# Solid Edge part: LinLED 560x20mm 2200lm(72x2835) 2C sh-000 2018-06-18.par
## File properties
Subject: LinLED 560x20mm 2200lm(72x2835) 2C
Author: radoslaw.kuczynski
Template: iso metric part.par
Last saved by: radoslaw.kuczynski
Revision: 2
Application: Solid Edge
Username: radoslaw.kuczynski
Gęstość: 0,000 kg/m^3
Dokładność: 0,990
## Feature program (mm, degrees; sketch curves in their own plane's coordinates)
body "unnamed Body 1"
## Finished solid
Body 1: solid body, 1821 faces, 4718 edges, 3074 vertices, 3 separate solids.
  Faces by surface: plane 1492, cylinder 147, spline 96, cone 30, swept 22, sphere 16, torus 10, spun 8
  Edges by curve: line 4024, curve on surface 358, circle 206, ellipse 66, spline 60, intersection 4
Bounding box of the edges (mm; curved faces can reach further): 560.000 x 4.500 x 20.000, from (-280, -3.5, -10) to (280, 1, 10).
Cylindrical faces by radius (mm): R0.2 x46, R0.2169 x6, R0.25 x12, R0.3373 x6, R0.4 x8, R0.4006 x2, R0.4008 x2, R0.525 x2, R0.6 x20, R0.75 x1, R1 x8, R1.1 x4, R1.2 x10, R2.15 x20
Conical faces (half-angle, radius in mm at the cone's reference point): 0.5 deg R0.5056 x4, 0.5 deg R1.0082 x4, 1 deg R0.5511 x2, 10 deg R0.2132 x4, 10 deg R0.4132 x4, 18.8604 deg R1.0669 x4, 27.363 deg R0.6214 x2, 45 deg R0.575 x2, 45 deg R0.625 x4
Toroidal faces (ring radius, tube radius in mm): R0.8 r0.2 x4, R0.8522 r0.3 x2, R0.9002 r0.2 x2, R0.9018 r0.2 x2
Spherical faces by radius (mm): R0.2 x12, R0.6 x4
Planar faces by outward normal: +x 191, +y 13, +z 191, -x 191, -y 259, -z 193, oblique 454
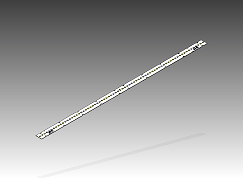
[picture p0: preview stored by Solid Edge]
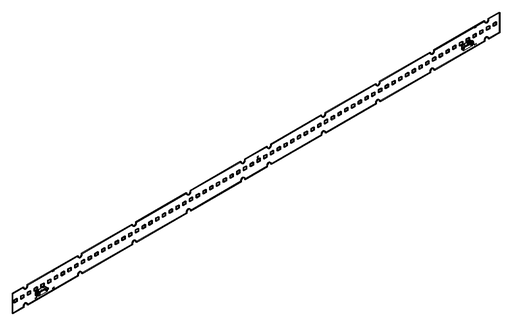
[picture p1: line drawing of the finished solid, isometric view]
